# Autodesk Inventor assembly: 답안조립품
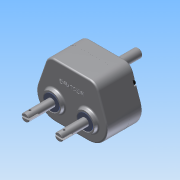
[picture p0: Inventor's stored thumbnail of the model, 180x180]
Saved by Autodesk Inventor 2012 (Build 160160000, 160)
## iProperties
Created: 2014-12
Part Number: 답안조립품
Document SubType Name: Assembly
Designer: Owner
Author: Owner
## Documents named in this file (14)
- C:\Documents and Settings\Owner\바탕 화면\441208V1022\답안조립품.iam
- C:\Documents and Settings\Owner\바탕 화면\441208V1022\1-본체.ipt
- C:\Documents and Settings\Owner\바탕 화면\441208V1022\서브축.ipt
- C:\Documents and Settings\Owner\바탕 화면\441208V1022\베어링- 6202.ipt
- C:\Documents and Settings\Owner\바탕 화면\441208V1022\메인축.ipt
- C:\Documents and Settings\Owner\바탕 화면\441208V1022\베어링- 6203.ipt
- C:\Documents and Settings\Owner\바탕 화면\441208V1022\오일시일-D-15.ipt
- C:\Documents and Settings\Owner\바탕 화면\441208V1022\메인기어.ipt
- C:\Documents and Settings\Owner\바탕 화면\441208V1022\키5x5.ipt
- C:\Documents and Settings\Owner\바탕 화면\441208V1022\멈춤링.ipt
- C:\Documents and Settings\Owner\바탕 화면\441208V1022\서브기어.ipt
- C:\Documents and Settings\Owner\바탕 화면\441208V1022\커버.ipt
- C:\Documents and Settings\Owner\바탕 화면\441208V1022\오일시일-D-17.ipt
- C:\Documents and Settings\Owner\바탕 화면\441208V1022\M 5 x 35.ipt
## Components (16 placed, 7 different names)
1. 1-본체:1
2. KS B 2023 6202 - 15 x 35 x 11:1
3. KS B 2023 6202 - 15 x 35 x 11:2
4. KS B 2023 6203 - 17 x 40 x 12:1
5. KS B 2804 D D - 15 30 7:1
6. KS B 2804 D D - 15 30 7:2
7. KS B 1336 17 x 1:1
8. KS B 1336 17 x 1:2
9. KS B 1336 17 x 1:3
10. KS B 2023 6203 - 17 x 40 x 12:2
11. KS B 2023 6203 - 17 x 40 x 12:3
12. KS B 2023 6203 - 17 x 40 x 12:4
13. KS B 2804 D D - 17 30 8:1
14. KS B 1003 - 미터 M 5 x 35:1
15. KS B 1003 - 미터 M 5 x 35:2
16. KS B 1003 - 미터 M 5 x 35:3
